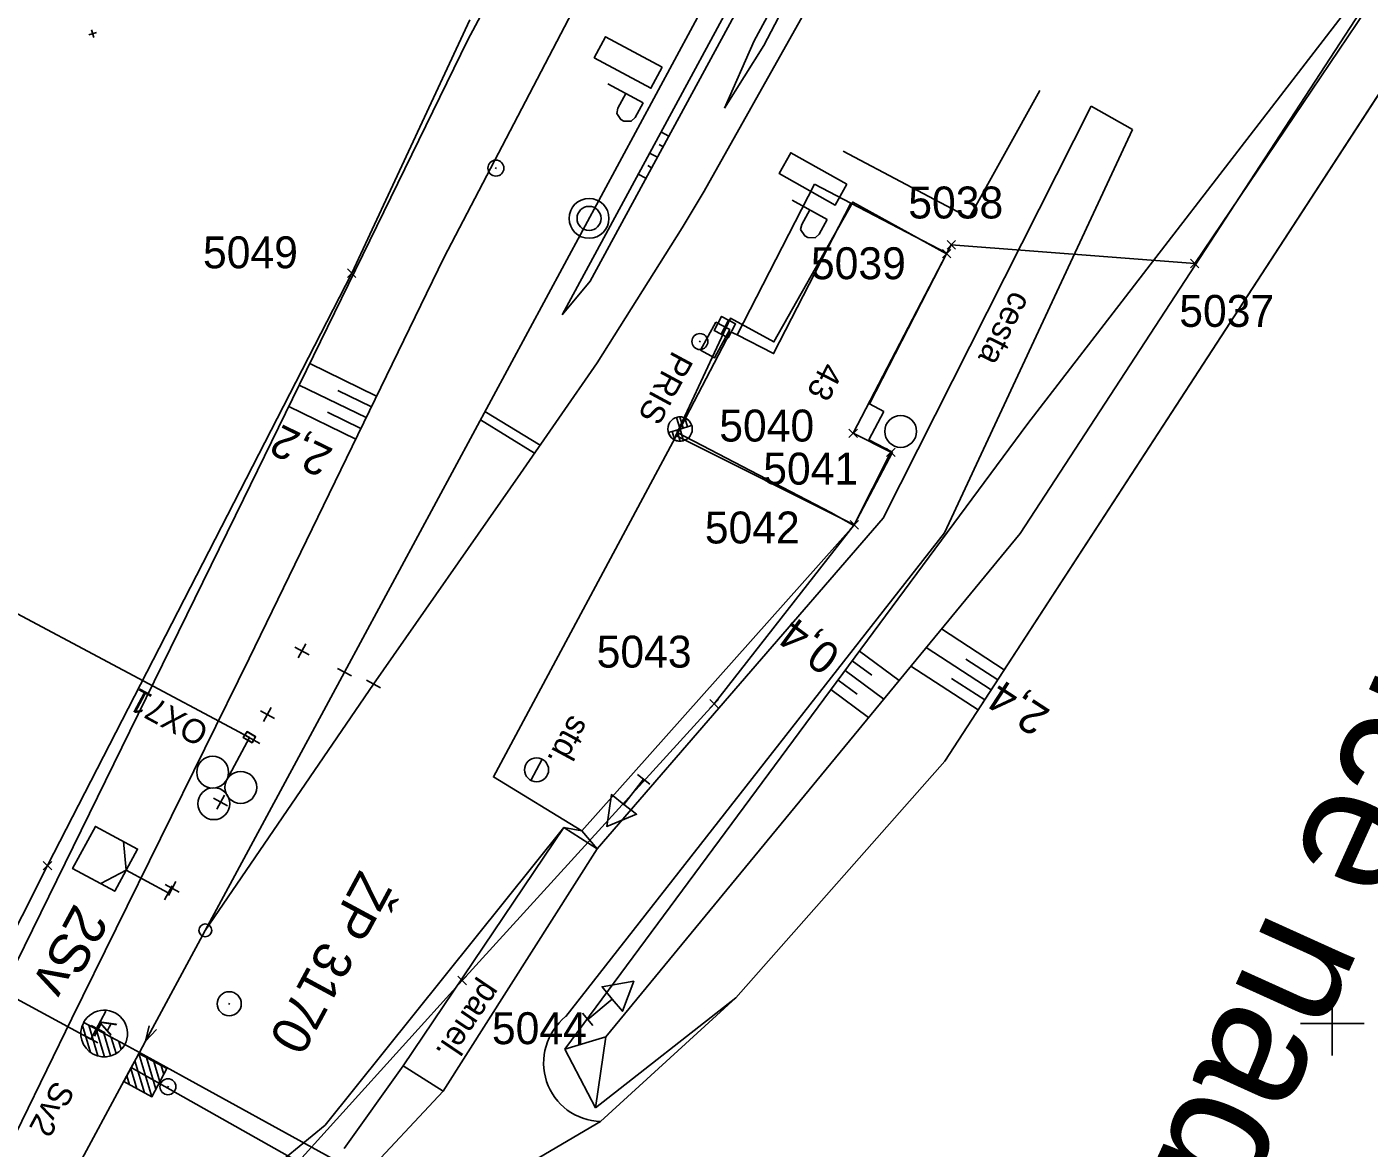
# Model space of a CAD drawing. Extents: x -795094 to -794639, y -1135368 to -1134681.
# Drawn here: x -794881.8 to -794797.7, y -1135007.8 to -1134937.6 of the extents above; entities that cross this region are included whole.
import ezdxf

# ---------------------------------------------------------------- set-up
doc = ezdxf.new("R2010")
doc.units = 0
for name, color, linetype in [('0381KM005-009P - Vrstva 1', 7, 'Continuous'), ('0381KM005-009P - Vrstva 12', 7, 'Continuous'), ('0381KM005-009P - Vrstva 16', 7, 'Continuous'), ('0381KM005-009P - Vrstva 17', 7, 'Continuous'), ('0381KM005-009P - Vrstva 2', 7, 'Continuous'), ('0381KM005-009P - Vrstva 23', 7, 'Continuous'), ('0381KM005-009P - Vrstva 25', 7, 'Continuous'), ('0381KM005-009P - Vrstva 28', 7, 'Continuous'), ('0381KM005-009P - Vrstva 3', 7, 'Continuous'), ('0381KM005-009P - Vrstva 33', 7, 'Continuous'), ('0381KM005-009P - Vrstva 4', 7, 'Continuous'), ('0381KM005-009P - Vrstva 41', 7, 'Continuous'), ('0381KM005-009P - Vrstva 43', 7, 'Continuous'), ('0381KM005-009P - Vrstva 48', 7, 'Continuous'), ('0381KM005-009P - Vrstva 49', 7, 'Continuous'), ('0381KM005-009P - Vrstva 51', 7, 'Continuous'), ('0381KM005-009P - Vrstva 55', 7, 'Continuous'), ('0381KM005-009P - Vrstva 57', 7, 'Continuous'), ('0381KM005-009P - Vrstva 6', 7, 'Continuous'), ('0381KM005-009P - Vrstva 7', 7, 'Continuous'), ('0381KM005-009P - Vrstva 8', 7, 'Continuous'), ('krizky_1000 - Vrstva 1', 7, 'Continuous'), ('szdc - hran DP', 7, 'Continuous'), ('szdc - szdc_cislo', 7, 'Continuous'), ('szdc - szdc_krizek', 7, 'Continuous'), ('vyt_sit - ohrožené', 7, 'Continuous'), ('vyt_sit - stávající', 7, 'Continuous')]:
    doc.layers.add(name, color=color, linetype=linetype)

msp = doc.modelspace()

# ---------------------------------------------------------------- linework, layer by layer
at = {"layer": '0381KM005-009P - Vrstva 1'}
for points in [[(-794788.584, -1134840.279), (-794803.188, -1134868.16), (-794810.376, -1134881.864), (-794818.661, -1134897.596), (-794826.62, -1134912.502), (-794834.335, -1134926.852), (-794861.916, -1134977.994)], [(-794786.958, -1134841.365), (-794793.838, -1134858.325), (-794800.908, -1134874.123), (-794807.726, -1134887.87), (-794826.516, -1134924.295), (-794833.336, -1134937.128), (-794839.366, -1134947.862), (-794840.749, -1134950.163), (-794846.082, -1134958.608), (-794850.879, -1134965.553), (-794860.098, -1134978.738)], [(-794861.916, -1134977.994), (-794870.638, -1134994.169), (-794874.381, -1135001.111), (-794874.769, -1135001.818)], [(-794860.098, -1134978.738), (-794870.638, -1134994.169), (-794874.381, -1135001.111), (-794874.769, -1135001.818)], [(-794874.769, -1135001.818), (-794875.274, -1135002.762), (-794882.938, -1135016.954), (-794888.877, -1135027.929)]]:
    msp.add_lwpolyline(points, dxfattribs=at)
at = {"layer": '0381KM005-009P - Vrstva 12'}
for p, q in [((-794868.254, -1134982.095), (-794868.254, -1134982.093)), ((-794867.486, -1134982.03), (-794867.487, -1134982.039)), ((-794867.706, -1134982.41), (-794867.706, -1134982.408))]:
    msp.add_line(p, q, dxfattribs=at)
msp.add_lwpolyline([(-794868.02, -1134981.72), (-794868.254, -1134982.095), (-794867.706, -1134982.41), (-794867.486, -1134982.03), (-794868.02, -1134981.72), (-794868.02, -1134981.729), (-794868.254, -1134982.093), (-794867.706, -1134982.408), (-794867.487, -1134982.039), (-794868.02, -1134981.729)], dxfattribs=at)
at = {"layer": '0381KM005-009P - Vrstva 16'}
for p, q in [((-794848.162, -1134987.718), (-794858.241, -1135002.662)), ((-794846.073, -1134989.059), (-794848.162, -1134987.718)), ((-794848.162, -1134987.718), (-794847.031, -1134987.928)), ((-794847.031, -1134987.928), (-794846.073, -1134989.059)), ((-794858.241, -1135002.662), (-794855.733, -1135004.243))]:
    msp.add_line(p, q, dxfattribs=at)
at = {"layer": '0381KM005-009P - Vrstva 17'}
for points in [[(-794818.322, -1134941.565), (-794822.763, -1134949.535), (-794830.659, -1134945.363)], [(-794829.977, -1134968.799), (-794847.031, -1134987.928), (-794852.583, -1134984.556), (-794841.01, -1134963.005)]]:
    msp.add_lwpolyline(points, dxfattribs=at)
at = {"layer": '0381KM005-009P - Vrstva 2'}
for p, q in [((-794862.356, -1134977.757), (-794861.476, -1134978.231)), ((-794860.098, -1134978.738), (-794870.638, -1134994.169)), ((-794859.658, -1134978.975), (-794860.538, -1134978.501)), ((-794877.832, -1135001.815), (-794878.34, -1135000.119)), ((-794878.261, -1134999.938), (-794875.685, -1135001.328)), ((-794878.261, -1134999.938), (-794878.261, -1134999.938)), ((-794877.369, -1135002.038), (-794877.947, -1135000.107)), ((-794876.956, -1135002.093), (-794877.474, -1135000.362)), ((-794876.576, -1135002.038), (-794877, -1135000.617)), ((-794876.224, -1135001.888), (-794876.528, -1135000.873)), ((-794875.905, -1135001.629), (-794876.055, -1135001.128)), ((-794875.685, -1135001.327), (-794874.769, -1135001.818)), ((-794830.917, -1135025.882), (-794874.769, -1135001.818))]:
    msp.add_line(p, q, dxfattribs=at)
for points in [[(-794861.916, -1134977.994), (-794870.638, -1134994.169), (-794874.381, -1135001.111), (-794874.769, -1135001.818)], [(-794874.15, -1135000.138), (-794874.381, -1135001.111), (-794873.695, -1135000.384)]]:
    msp.add_lwpolyline(points, dxfattribs=at)
msp.add_circle((-794870.638, -1134994.169), 0.4, dxfattribs=at)
for centre, radius, start, end in [((-794876.971, -1135000.632), 1.462, 331.59731, 152.06683), ((-794876.972, -1135000.633), 1.464, 151.68684, 331.64769)]:
    msp.add_arc(centre, radius, start, end, dxfattribs=at)
at = {"layer": '0381KM005-009P - Vrstva 23'}
for p, q in [((-794832.457, -1134947.423), (-794837.307, -1134956.855)), ((-794830.175, -1134948.613), (-794832.457, -1134947.423)), ((-794830.175, -1134948.613), (-794824.165, -1134951.751)), ((-794837.718, -1134956.673), (-794841.01, -1134963.005)), ((-794837.307, -1134956.855), (-794837.718, -1134956.673)), ((-794828.114, -1134961.663), (-794829.042, -1134963.435)), ((-794841.01, -1134963.005), (-794831.42, -1134967.988)), ((-794829.042, -1134963.435), (-794827.571, -1134964.205)), ((-794829.977, -1134968.799), (-794827.571, -1134964.205)), ((-794831.42, -1134967.988), (-794829.977, -1134968.799))]:
    msp.add_line(p, q, dxfattribs=at)
for points in [[(-794830.175, -1134948.613), (-794835.018, -1134958.032), (-794837.307, -1134956.855)], [(-794824.165, -1134951.751), (-794829.015, -1134961.183), (-794828.114, -1134961.663)]]:
    msp.add_lwpolyline(points, dxfattribs=at)
at = {"layer": '0381KM005-009P - Vrstva 25'}
msp.add_lwpolyline([(-794838.642, -1134956.06), (-794837.762, -1134956.534), (-794838.712, -1134958.294), (-794839.592, -1134957.82), (-794838.642, -1134956.06)], dxfattribs=at)
at = {"layer": '0381KM005-009P - Vrstva 28'}
for p, q in [((-794839.66, -1134957.325), (-794839.612, -1134957.237)), ((-794872.954, -1135003.918), (-794873.002, -1135004.006))]:
    msp.add_line(p, q, dxfattribs=at)
for centre in [(-794839.636, -1134957.281), (-794872.978, -1135003.962)]:
    msp.add_circle(centre, 0.5, dxfattribs=at)
at = {"layer": '0381KM005-009P - Vrstva 3'}
for p, q in [((-794873.988, -1135004.591), (-794874.8, -1135001.882)), ((-794873.736, -1135004.125), (-794874.333, -1135002.133)), ((-794874.922, -1135004.088), (-794875.303, -1135002.816)), ((-794874.454, -1135004.34), (-794875.051, -1135002.348)), ((-794873.484, -1135003.657), (-794873.866, -1135002.385)), ((-794873.233, -1135003.191), (-794873.399, -1135002.637)), ((-794875.388, -1135003.836), (-794875.554, -1135003.282))]:
    msp.add_line(p, q, dxfattribs=at)
msp.add_lwpolyline([(-794875.748, -1135003.642), (-794874.8, -1135001.882), (-794873.039, -1135002.831), (-794873.988, -1135004.591)], close=True, dxfattribs=at)
msp.add_lwpolyline([(-794875.274, -1135002.762), (-794845.796, -1135019.381), (-794847.666, -1135022.537), (-794833.282, -1135030.23)], dxfattribs=at)
at = {"layer": '0381KM005-009P - Vrstva 33'}
for points in [[(-794842.003, -1134940.102), (-794842.709, -1134941.412), (-794846.255, -1134939.5), (-794845.549, -1134938.189)], [(-794830.423, -1134947.433), (-794831.152, -1134948.731), (-794834.665, -1134946.758), (-794833.936, -1134945.46)]]:
    msp.add_lwpolyline(points, close=True, dxfattribs=at)
for points in [[(-794845.404, -1134941.145), (-794843.197, -1134942.335)], [(-794844.782, -1134942.666), (-794844.287, -1134941.748)], [(-794843.197, -1134942.335), (-794843.692, -1134943.253)], [(-794843.692, -1134943.253), (-794843.934, -1134943.482), (-794844.397, -1134943.483), (-794844.591, -1134943.378), (-794844.852, -1134942.986), (-794844.782, -1134942.666)], [(-794833.842, -1134948.418), (-794831.656, -1134949.646)], [(-794833.246, -1134949.949), (-794832.735, -1134949.04)], [(-794832.167, -1134950.555), (-794832.413, -1134950.779), (-794832.875, -1134950.773), (-794833.068, -1134950.665), (-794833.322, -1134950.269), (-794833.246, -1134949.949)], [(-794831.656, -1134949.646), (-794832.167, -1134950.555)]]:
    msp.add_lwpolyline(points, dxfattribs=at)
at = {"layer": '0381KM005-009P - Vrstva 4'}
msp.add_line((-794840.749, -1134950.163), (-794839.366, -1134947.862), dxfattribs=at)
at = {"layer": '0381KM005-009P - Vrstva 41'}
msp.add_line((-794849.515, -1134983.447), (-794850.229, -1134984.771), dxfattribs=at)
msp.add_circle((-794849.872, -1134984.109), 0.752, dxfattribs=at)
at = {"layer": '0381KM005-009P - Vrstva 43'}
msp.add_lwpolyline([(-794837.834, -1134955.942), (-794837.394, -1134956.179), (-794837.868, -1134957.059), (-794838.748, -1134956.585), (-794838.274, -1134955.705), (-794837.834, -1134955.942), (-794838.308, -1134956.822)], dxfattribs=at)
msp.add_circle((-794827.05, -1134962.911), 1, dxfattribs=at)
at = {"layer": '0381KM005-009P - Vrstva 48'}
for p, q in [((-794841.587, -1134944.418), (-794842.074, -1134944.153)), ((-794841.945, -1134945.077), (-794842.188, -1134944.945)), ((-794842.303, -1134945.736), (-794842.788, -1134945.473)), ((-794843.019, -1134947.054), (-794843.502, -1134946.792)), ((-794842.661, -1134946.395), (-794842.903, -1134946.264)), ((-794859.9, -1134960.697), (-794864.091, -1134958.659)), ((-794860.556, -1134962.046), (-794864.749, -1134960.007)), ((-794860.228, -1134961.371), (-794862.324, -1134960.352)), ((-794861.212, -1134963.395), (-794865.408, -1134961.354)), ((-794860.884, -1134962.72), (-794862.981, -1134961.7)), ((-794820.559, -1134977.843), (-794824.489, -1134975.286)), ((-794829.639, -1134976.677), (-794827.152, -1134978.519)), ((-794821.377, -1134979.101), (-794825.449, -1134976.451)), ((-794830.532, -1134977.883), (-794828.106, -1134979.679)), ((-794830.086, -1134977.28), (-794828.857, -1134978.19)), ((-794822.195, -1134980.358), (-794826.408, -1134977.616)), ((-794820.968, -1134978.472), (-794822.969, -1134977.17)), ((-794830.978, -1134978.486), (-794829.781, -1134979.372)), ((-794821.786, -1134979.729), (-794823.857, -1134978.381)), ((-794831.424, -1134979.089), (-794829.061, -1134980.838))]:
    msp.add_line(p, q, dxfattribs=at)
at = {"layer": '0381KM005-009P - Vrstva 49'}
for p, q in [((-794837.684, -1134907.328), (-794854.176, -1134938.373)), ((-794840.647, -1134923.239), (-794855.687, -1134952.034)), ((-794792.988, -1134928.575), (-794819.559, -1134969.298)), ((-794792.988, -1134928.575), (-794819.082, -1134962.417)), ((-794790.5, -1134931.648), (-794824.29, -1134983.577)), ((-794877.455, -1134937.92), (-794877.935, -1134938.064)), ((-794877.767, -1134937.752), (-794877.623, -1134938.232)), ((-794854.176, -1134938.373), (-794868.24, -1134967.149)), ((-794855.687, -1134952.034), (-794867.891, -1134977.129)), ((-794819.082, -1134962.417), (-794848.099, -1135001.612)), ((-794868.24, -1134967.149), (-794883.505, -1134998.267)), ((-794819.559, -1134969.298), (-794845.522, -1135000.83)), ((-794867.891, -1134977.129), (-794879, -1134999.695)), ((-794837.373, -1134998.386), (-794824.29, -1134983.577)), ((-794863.119, -1135006.371), (-794848.162, -1134987.718)), ((-794858.241, -1135002.662), (-794848.162, -1134987.718)), ((-794846.173, -1135005.288), (-794837.373, -1134998.386)), ((-794879, -1134999.695), (-794890.343, -1135022.912)), ((-794845.522, -1135000.83), (-794848.099, -1135001.612)), ((-794845.522, -1135000.83), (-794846.173, -1135005.288)), ((-794848.099, -1135001.612), (-794846.173, -1135005.288)), ((-794858.241, -1135002.662), (-794861.943, -1135007.826)), ((-794863.119, -1135006.371), (-794872.471, -1135014.016))]:
    msp.add_line(p, q, dxfattribs=at)
for points in [[(-794815.371, -1134894.435), (-794815.665, -1134896.209), (-794830.438, -1134923.896), (-794846.524, -1134953.505), (-794848.275, -1134955.609)], [(-794815.371, -1134894.435), (-794830.99, -1134923.676), (-794848.275, -1134955.609)], [(-794813.726, -1134895.612), (-794815.698, -1134900.493), (-794822.002, -1134912.521), (-794829.492, -1134927.011), (-794835.621, -1134938.728), (-794838.097, -1134942.656)], [(-794813.726, -1134895.612), (-794816.272, -1134900.056), (-794822.552, -1134912.269), (-794829.828, -1134926.6), (-794836.239, -1134938.447), (-794838.097, -1134942.656)]]:
    msp.add_lwpolyline(points, dxfattribs=at)
at = {"layer": '0381KM005-009P - Vrstva 51'}
for p, q in [((-794815.11, -1134942.54), (-794828.146, -1134968.345)), ((-794815.11, -1134942.54), (-794812.52, -1134943.998)), ((-794812.52, -1134943.998), (-794824.295, -1134969.269)), ((-794828.146, -1134968.345), (-794846.073, -1134989.059)), ((-794824.295, -1134969.269), (-794848.049, -1134999.571)), ((-794842.768, -1134985.014), (-794843.556, -1134984.398)), ((-794846.073, -1134989.059), (-794855.733, -1135004.243)), ((-794846.987, -1134999.359), (-794846.349, -1135000.129)), ((-794855.733, -1135004.243), (-794871.739, -1135021.338))]:
    msp.add_line(p, q, dxfattribs=at)
for points in [[(-794871.739, -1135021.338), (-794845.859, -1135006.134), (-794837.373, -1134998.386), (-794824.29, -1134983.577), (-794790.5, -1134931.648), (-794766.188, -1134894.559)], [(-794843.162, -1134984.706), (-794844.394, -1134986.281), (-794845.182, -1134985.665), (-794845.473, -1134987.66), (-794843.607, -1134986.897), (-794844.394, -1134986.281)], [(-794846.668, -1134999.744), (-794845.128, -1134998.468), (-794844.49, -1134999.238), (-794843.78, -1134997.351), (-794845.766, -1134997.698), (-794845.128, -1134998.468)]]:
    msp.add_lwpolyline(points, dxfattribs=at)
msp.add_ellipse((-794845.742, -1135002.436), major_axis=(-2.169, -3.012), ratio=0.990529, start_param=4.446216, end_param=6.879975, dxfattribs=at)
at = {"layer": '0381KM005-009P - Vrstva 55'}
msp.add_lwpolyline([(-794829.96, -1134968.76), (-794841.15, -1134963.17), (-794837.72, -1134955.82), (-794835, -1134957.3), (-794830.05, -1134948.55), (-794824.17, -1134951.78), (-794830.03, -1134963.03), (-794827.67, -1134964.22), (-794829.96, -1134968.76)], dxfattribs=at)
at = {"layer": '0381KM005-009P - Vrstva 6'}
for p, q in [((-794877.804, -1135000.976), (-794918.759, -1134978.921)), ((-794876.865, -1134999.233), (-794877.804, -1135000.976)), ((-794878.244, -1135000.739), (-794877.364, -1135001.213))]:
    msp.add_line(p, q, dxfattribs=at)
at = {"layer": '0381KM005-009P - Vrstva 7'}
for p, q in [((-794852.398, -1134946.375), (-794852.446, -1134946.463)), ((-794853.107, -1134961.66), (-794849.652, -1134963.777)), ((-794853.392, -1134962.189), (-794849.993, -1134964.271)), ((-794864.338, -1134976.225), (-794864.812, -1134977.105)), ((-794864.135, -1134976.902), (-794865.015, -1134976.428)), ((-794866.304, -1134980.89), (-794867.184, -1134980.416)), ((-794866.507, -1134980.213), (-794866.981, -1134981.093)), ((-794870.117, -1134985.893), (-794869.237, -1134986.367)), ((-794869.914, -1134986.57), (-794869.44, -1134985.69)), ((-794875.599, -1134990.397), (-794872.958, -1134991.821)), ((-794873.195, -1134992.261), (-794872.721, -1134991.381)), ((-794873.156, -1134991.305), (-794872.276, -1134991.779)), ((-794872.953, -1134991.982), (-794872.479, -1134991.102)), ((-794877.793, -1135000.12), (-794876.913, -1135000.594)), ((-794877.59, -1135000.797), (-794877.116, -1134999.917))]:
    msp.add_line(p, q, dxfattribs=at)
for points in [[(-794875.599, -1134990.397), (-794874.887, -1134989.077), (-794877.527, -1134987.653), (-794878.951, -1134990.294), (-794876.311, -1134991.718), (-794875.599, -1134990.397)], [(-794877.192, -1134991.242), (-794875.599, -1134990.397), (-794875.769, -1134988.601)]]:
    msp.add_lwpolyline(points, dxfattribs=at)
for centre, radius in [((-794852.422, -1134946.419), 0.5), ((-794846.585, -1134949.567), 1.246), ((-794846.585, -1134949.567), 0.752)]:
    msp.add_circle(centre, radius, dxfattribs=at)
at = {"layer": '0381KM005-009P - Vrstva 8'}
for p, q in [((-794867.871, -1134982.096), (-794910.227, -1134959.525)), ((-794867.871, -1134982.096), (-794869.295, -1134984.737)), ((-794867.211, -1134982.452), (-794868.531, -1134981.74))]:
    msp.add_line(p, q, dxfattribs=at)
for centre in [(-794870.175, -1134984.262), (-794868.415, -1134985.211), (-794870.102, -1134986.233)]:
    msp.add_circle(centre, 1, dxfattribs=at)
at = {"layer": 'krizky_1000 - Vrstva 1'}
for points in [[(-794800, -1134998), (-794800, -1135002)], [(-794802, -1135000), (-794798, -1135000)]]:
    msp.add_lwpolyline(points, dxfattribs=at)
at = {"layer": 'szdc - hran DP'}
for p, q in [((-794771.93, -1134898.11), (-794808.62, -1134952.39)), ((-794861.46, -1134953), (-794854.06, -1134937.12)), ((-794824.17, -1134951.78), (-794830.03, -1134963.03)), ((-794823.88, -1134951.22), (-794824.17, -1134951.78)), ((-794808.62, -1134952.39), (-794823.88, -1134951.22)), ((-794880.53, -1134990.11), (-794861.46, -1134953)), ((-794830.03, -1134963.03), (-794827.67, -1134964.22)), ((-794827.67, -1134964.22), (-794829.96, -1134968.76)), ((-794829.96, -1134968.76), (-794838.74, -1134979.98)), ((-794838.74, -1134979.98), (-794854.54, -1134997.31)), ((-794899.86, -1135028.32), (-794880.53, -1134990.11)), ((-794854.54, -1134997.31), (-794868.85, -1135013.13))]:
    msp.add_line(p, q, dxfattribs=at)
at = {"layer": 'szdc - szdc_krizek'}
for p, q in [((-794823.615, -1134951.485), (-794824.146, -1134950.955)), ((-794824.146, -1134951.485), (-794823.615, -1134950.955)), ((-794823.905, -1134952.045), (-794824.436, -1134951.515)), ((-794824.436, -1134952.045), (-794823.905, -1134951.515)), ((-794808.355, -1134952.655), (-794808.886, -1134952.125)), ((-794808.886, -1134952.655), (-794808.355, -1134952.125)), ((-794861.195, -1134953.265), (-794861.726, -1134952.735)), ((-794861.726, -1134953.265), (-794861.195, -1134952.735)), ((-794829.765, -1134963.295), (-794830.296, -1134962.765)), ((-794830.296, -1134963.295), (-794829.765, -1134962.765)), ((-794827.405, -1134964.485), (-794827.936, -1134963.955)), ((-794827.936, -1134964.485), (-794827.405, -1134963.955)), ((-794829.695, -1134969.025), (-794830.226, -1134968.495)), ((-794830.226, -1134969.025), (-794829.695, -1134968.495)), ((-794838.475, -1134980.245), (-794839.006, -1134979.715)), ((-794839.006, -1134980.245), (-794838.475, -1134979.715)), ((-794880.265, -1134990.375), (-794880.796, -1134989.845)), ((-794880.796, -1134990.375), (-794880.265, -1134989.845)), ((-794854.275, -1134997.575), (-794854.806, -1134997.045)), ((-794854.806, -1134997.575), (-794854.275, -1134997.045))]:
    msp.add_line(p, q, dxfattribs=at)
at = {"layer": 'vyt_sit - ohrožené'}
msp.add_line((-794869.114, -1134998.723), (-794869.162, -1134998.811), dxfattribs=at)
msp.add_circle((-794869.138, -1134998.767), 0.756, dxfattribs=at)
at = {"layer": 'vyt_sit - stávající'}
for p, q in [((-794841.611, -1134962.985), (-794840.879, -1134962.763)), ((-794840.879, -1134962.763), (-794841.096, -1134962.03)), ((-794840.901, -1134962.002), (-794840.691, -1134962.705)), ((-794840.152, -1134962.541), (-794840.879, -1134962.763)), ((-794840.879, -1134962.763), (-794840.657, -1134963.499)), ((-794840.57, -1134962.063), (-794840.404, -1134962.618)), ((-794841.365, -1134962.91), (-794841.202, -1134963.455)), ((-794841.077, -1134962.824), (-794840.868, -1134963.524))]:
    msp.add_line(p, q, dxfattribs=at)
msp.add_circle((-794840.879, -1134962.763), 0.764, dxfattribs=at)
for radius, start, end in [(0.764, 16.1849, 106.50291), (0.765, 196.87373, 286.76723)]:
    msp.add_arc((-794840.879, -1134962.763), radius, start, end, dxfattribs=at)

# ---------------------------------------------------------------- texts
at = {"layer": '0381KM005-009P - Vrstva 16'}
msp.add_text('panel.', height=1.5, rotation=236.00225, dxfattribs=at).set_placement((-794853.21, -1134997.208))
at = {"layer": '0381KM005-009P - Vrstva 2'}
msp.add_text('2Sv', height=2.5, rotation=241.66726, dxfattribs=at).set_placement((-794878.811, -1134992.402))
at = {"layer": '0381KM005-009P - Vrstva 23'}
msp.add_text('žst. Strunkovice nad Volyňkou', height=8, rotation=245.66299, dxfattribs=at).set_placement((-794771.538, -1134921.216))
at = {"layer": '0381KM005-009P - Vrstva 25'}
msp.add_text('PRIS', height=1.5, rotation=241.66191, dxfattribs=at).set_placement((-794841.32, -1134957.796))
at = {"layer": '0381KM005-009P - Vrstva 41'}
msp.add_text('std.', height=1.5, rotation=241.66191, dxfattribs=at).set_placement((-794847.719, -1134980.594))
at = {"layer": '0381KM005-009P - Vrstva 48'}
for s, rotation, p in [('2,2', 154.06579, (-794862.537, -1134964.052)), ('0,4', 143.48656, (-794830.703, -1134976.676)), ('2,4', 146.9481, (-794817.586, -1134980.427))]:
    msp.add_text(s, height=2, rotation=rotation, dxfattribs=at).set_placement(p)
at = {"layer": '0381KM005-009P - Vrstva 51'}
msp.add_text('cesta', height=1.5, rotation=243.19831, dxfattribs=at).set_placement((-794820.059, -1134954.019))
at = {"layer": '0381KM005-009P - Vrstva 57'}
msp.add_text('43', height=1.5, rotation=242.78017, dxfattribs=at).set_placement((-794831.942, -1134958.488))
at = {"layer": '0381KM005-009P - Vrstva 6'}
for s, height, rotation, p in [('  A ', 1, 61.67637, (-794876.924, -1135001.45)), ('Sv2', 1.5, 241.67637, (-794880.085, -1135003.496))]:
    msp.add_text(s, height=height, rotation=rotation, dxfattribs=at).set_placement(p)
at = {"layer": '0381KM005-009P - Vrstva 8'}
msp.add_text('OX71', height=1.5, rotation=151.66525, dxfattribs=at).set_placement((-794870.315, -1134981.384))
at = {"layer": 'szdc - szdc_cislo'}
for s, p in [('5038', (-794826.574, -1134949.572)), ('5049', (-794870.782, -1134952.693)), ('5039', (-794832.675, -1134953.377)), ('5037', (-794809.589, -1134956.363)), ('5040', (-794838.422, -1134963.546)), ('5041', (-794835.666, -1134966.244)), ('5042', (-794839.327, -1134969.931)), ('5043', (-794846.106, -1134977.706)), ('5044', (-794852.672, -1135001.297))]:
    msp.add_text(s, height=2, dxfattribs=at).set_placement(p)
at = {"layer": 'vyt_sit - ohrožené'}
msp.add_text('ŽP 3170', height=2.4, rotation=241.67136, dxfattribs=at).set_placement((-794860.936, -1134990.309))

doc.saveas('drawing.dxf')
